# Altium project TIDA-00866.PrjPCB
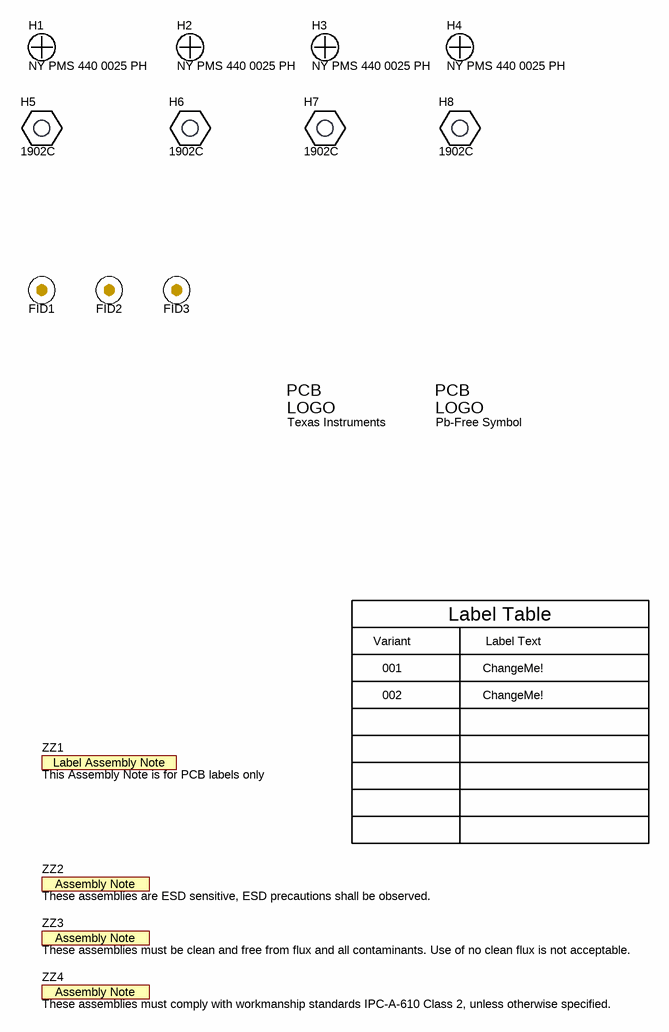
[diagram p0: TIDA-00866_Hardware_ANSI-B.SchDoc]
CopyrightYear: 2014; PCB_Layout: Who did the Layout?; PCB_Rev: E1; PRJ_Customer: Public Release; PRJ_Engineer: Enter name of project lead; PRJ_Number: XX####; PRJ_Title: Change in menu Project|Project Options|Parameters; SCH_Rev: E1; TechSupport: http://www.ti.com/support
2 sheets, 32 parts. Net scope: global (net labels, ports and power ports of the same name join across sheets).
Board file: TIDA-00866.PcbDoc
Sheets:
  TIDA-00866_Hardware_ANSI-B.SchDoc
  TIDA-00866.SchDoc

## Sheet TIDA-00866_Hardware_ANSI-B.SchDoc
size 431 x 279 mm; Date: Not shown in title block; ApprovedBy: Not shown in title block; CheckedBy: Not shown in title block; Author: Not shown in title block; CompanyName: Not shown in title block; Engineer: Not shown in title block; Organization: Not shown in title block; Address1: Not shown in title block; Address2: Not shown in title block; Address3: Not shown in title block; Address4: Not shown in title block; DocumentNumber: 1; Revision: Use project parameter SCH_Rev; SheetNumber: 1; SheetTotal: 1; PageSetup: Record=PageOptions|CenterHorizontal=True|CenterVertical=True|PrintScale=1.00|XCorrection=1.00|YCorrection=1.00|PrintKind=0|BorderSize=5000000|LeftOffset=0|BottomOffset=0|Orientation=2|PaperLength=1000|PaperWidth=1000|Scale=100|PaperSource=15|PrintQuality=600|MediaType=1|DitherType=10|PaperKind=Letter|PrintScaleMode=1

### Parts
FID1  Fiducial  [Fiducial10-20]  (value not drawn)
FID2  Fiducial  [Fiducial10-20]  (value not drawn)
FID3  Fiducial  [Fiducial10-20]  (value not drawn)
H1  NY PMS 440 0025 PH  [NY PMS 440 0025 PH]
H2  NY PMS 440 0025 PH  [NY PMS 440 0025 PH]
H3  NY PMS 440 0025 PH  [NY PMS 440 0025 PH]
H4  NY PMS 440 0025 PH  [NY PMS 440 0025 PH]
H5  1902C  [Keystone_1902C]
H6  1902C  [Keystone_1902C]
H7  1902C  [Keystone_1902C]
H8  1902C  [Keystone_1902C]
Logo1  Texas Instruments  [TI_Stacked_Overlay_Medium]  (no BOM)
Logo2  Pb-Free Symbol  [Pb-Free_Overlay_Small]  (no BOM)
ZZ1  This Assembly Note is for PCB labels only  [AssemblyNoteLabel]  (no BOM)
ZZ2  These assemblies are ESD sensitive, ESD precautions shall be observed.  [AssemblyNote]  (no BOM)
ZZ3  These assemblies must be clean and free from flux and all contaminants. Use of no clean flux is not acceptable.  [AssemblyNote]  (no BOM)
ZZ4  These assemblies must comply with workmanship standards IPC-A-610 Class 2, unless otherwise specified.  [AssemblyNote]  (no BOM)

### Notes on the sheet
- Variant
- Label Table
- Label Text
- 001
- 002
- ChangeMe!

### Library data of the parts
FID1-FID3 = Fiducial: Fiducial mark.  There is nothing to buy or mount.; SymbolCreator: codlsc
H1-H4 = NY PMS 440 0025 PH: Machine Screw, Round, #4-40 x 1/4, Nylon, Philips panhead; Manufacturer: B&F Fastener Supply; CompType: Hardware; SymbolCreator: codlsc; U/M: EA
H5-H8 = 1902C: Standoff, Hex, 0.5"L #4-40 Nylon; Manufacturer: Keystone; CompType: Hardware; SymbolCreator: a0412235
Logo1 = TI_Logo: Texas Instrument Corporate Signature; SymbolCreator: a0412235
Logo2 = Pb-Free: SymbolCreator: a0412235
ZZ1 = AssemblyNoteLabel: SymbolCreator: a0412235
ZZ2-ZZ4 = AssemblyNote: SymbolCreator: codlsc

## Sheet TIDA-00866.SchDoc
size A3; Date: Not shown in title block; ApprovedBy: Not shown in title block; CheckedBy: Not shown in title block; Author: Not shown in title block; CompanyName: Not shown in title block; DrawnBy: Alex Wang; Engineer: Not shown in title block; Organization: Not shown in title block; Address1: Not shown in title block; Address2: Not shown in title block; Address3: Not shown in title block; Address4: Not shown in title block; DocumentNumber: 1; Revision: Use project parameter SCH_Rev; SheetNumber: 1; SheetTotal: 1; PageSetup: Record=PageOptions¦CenterHorizontal=True¦CenterVertical=True¦PrintScale=0.68¦XCorrection=1.00¦YCorrection=1.00¦PrintKind=0¦BorderSize=5000000¦LeftOffset=0¦BottomOffset=0¦Orientation=2¦PaperLength=1000¦PaperWidth=1000¦Scale=100¦PaperSource=15¦PrintQuality=600¦MediaType=1¦DitherType=10¦PaperKind=Letter¦PrintScaleMode=1
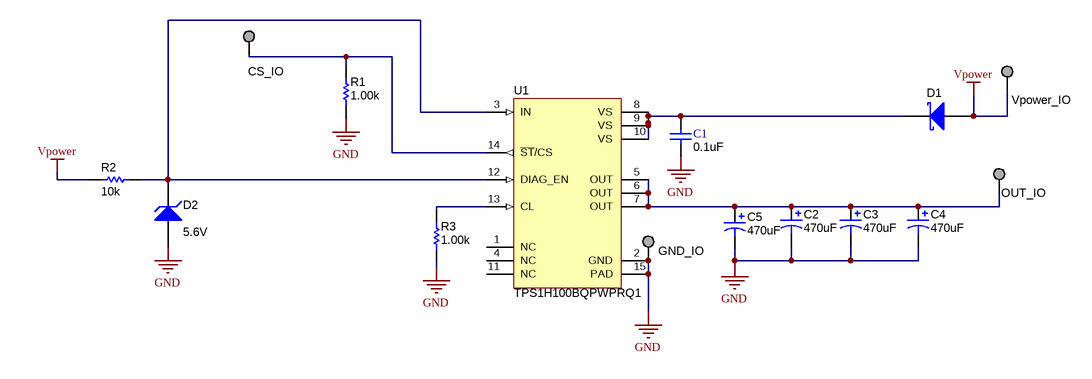
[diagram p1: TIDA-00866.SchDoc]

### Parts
C1  ValueDisplayed: 0.1uF  [0603]  (hidden comment: GRM188R71H104KA93D)
C2  ValueDisplayed: 470uF  [ZLH_1250x2500]  (hidden comment: 63ZLH470M12.5X25)
C3  ValueDisplayed: 470uF  [ZLH_1250x2500]  (hidden comment: 63ZLH470M12.5X25)
C4  ValueDisplayed: 470uF  [ZLH_1250x2500]  (hidden comment: 63ZLH470M12.5X25)
C5  ValueDisplayed: 470uF  [ZLH_1250x2500]  (hidden comment: 63ZLH470M12.5X25)
CS_IO  Suggest using a net name here  [Keystone1502-2]  (value not drawn)
D1  B350A-13-F  [SMA]  (value not drawn)
D2  value 5.6V  [powerDI123]  (hidden comment: DFLZ5V6-7)
GND_IO  Suggest using a net name here  [Keystone1502-2]  (value not drawn)
OUT_IO  Suggest using a net name here  [Keystone1502-2]  (value not drawn)
R1  ValueDisplayed: 1.00k  [0805_HV]  (hidden comment: CRCW08051K00FKEA)
R2  ValueDisplayed: 10k  [1206]  (hidden comment: CRCW120610K0JNEA)
R3  ValueDisplayed: 1.00k  [0805_HV]  (hidden comment: CRCW08051K00FKEA)
U1  TPS1H100BQPWPRQ1  [PWP0014C_N]
Vpower_IO  Suggest using a net name here  [Keystone1502-2]  (value not drawn)

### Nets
GND: C1.1 C2.2(-) C3.2(-) C4.2(-) C5.2(-) D2.2(A) GND_IO.1 R1.1 R3.1 U1.2(GND) U1.15(PAD)
Vpower: D1.2(A) R2.1 Vpower_IO.1
NetC1_2: C1.2 D1.1(K) U1.8(VS) U1.9(VS) U1.10(VS)
NetC2_1: C2.1(+) C3.1(+) C4.1(+) C5.1(+) OUT_IO.1 U1.5(OUT) U1.6(OUT) U1.7(OUT)
NetCS_IO_1: CS_IO.1 R1.2 U1.14(~{ST}/CS)
NetD2_1: D2.1(K) R2.2 U1.3(IN) U1.12(DIAG_EN)
NetR3_2: R3.2 U1.13(CL)

Not connected (* = marked no-connect by the designer): U1 1(NC) 4(NC) 11(NC)

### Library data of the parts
C1 = GRM188R71H104KA93D: CAP, CERM, 0.1uF, 50V, +/-10%, X7R, 0603; Manufacturer: MuRata; Polarized: N; CompType: Capacitor; U/M: EA; Cap_F: 0.0000001; Tolerance_%: 10; VDC_V: 50; TaMin_C: -55; TaMax_C: 125
C2-C5 = 63ZLH470M12.5X25: CAP, AL, 470 µF, 63 V, +/- 20%, 0.043 ohm, TH; Manufacturer: Rubycon; Polarized: Y; CompType: Capacitor; Value: 470uF; U/M: EA; Cap_F: 0.00047; Tolerance_%: 20; VDC_V: 63; Value2: 63V; ESR_ohm: 0.043; IRMS_A: 1.99; TaMin_C: -40; TaMax_C: 105
CS_IO GND_IO OUT_IO Vpower_IO = 1502-2: Terminal, Turret, TH, Double; Manufacturer: Keystone; CompType: Turret Terminal; U/M: EA
D1 = B350A-13-F: Diode, Schottky, 50 V, 3 A, SMA; Manufacturer: Diodes Inc.; U/M: EA; Vf_V: 0.7; Value: 50V; Value1: 3A; Value2: 0.7V; Io_A: 3; Vr_V: 50; TJmax_C: 125; RJC_CperW: 25
D2 = DFLZ5V6-7: Diode, Zener, 5.6 V, 1 W, PowerDI123; Manufacturer: Diodes Inc.; SymbolCreator: a0412235; U/M: EA; Power_W: 1; Vz_V: 5.6; Value1: 1W; RJA_CperW: 110
R1 R3 = CRCW08051K00FKEA: RES, 1.00 k, 1%, 0.125 W, 0805; Manufacturer: Vishay-Dale; CompType: Resistor; Value: 1.00k; Res_ohm: 1000; Value_Code: 1k00; Tolerance_%: 1; Power_W: 0.125; Value2: 0.125W; VDC_V: 150; TempCo: 100 ppm/C; EIA_Code: E96; U/M: EA
R2 = CRCW120610K0JNEA: RES, 10 k, 5%, 0.25 W, 1206; Manufacturer: Vishay-Dale; CompType: Resistor; Value: 10k; Res_ohm: 10000; Value_Code: 10k0; Tolerance_%: 5; Power_W: 0.25; Value2: 0.25W; VDC_V: 200; TempCo: 200 ppm/C; EIA_Code: E24; U/M: EA
U1 = TPS1H100BQPWPRQ1: TPS1H100-Q1 Single Channel Smart High Side Driver, PWP0014C; Alternate Manufacturer: None; Manufacturer: Texas Instruments; SymbolCreator: a0411947; CompType: IC; U/M: EA

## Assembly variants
001: not fitted FID1 FID2 FID3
